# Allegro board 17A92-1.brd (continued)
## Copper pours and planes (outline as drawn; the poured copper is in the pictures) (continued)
GND on TOP: 19.34,73.56 19.2,73.7 19.2,74.07 19.12,74.14 18.29,74.14 18.13,74.3 18.13,74.86 18.21,74.93 19.73,74.93 19.83,75.03 19.83,76.1 19.94,76.2 20.9,76.2 21.05,76.05 21.05,74.07 21,74.02 20.76,74.02 20.73,74.04 20.73,74.59 20.7,74.62 20.58,74.62 20.55,74.59 20.55,74.04 20.54,74.03 20.25,74.03 20.24,74.04 20.24,74.58 20.22,74.6 20.05,74.6 20.02,74.58 20.02,74.1 20.01,74.08 19.48,74.08 19.44,74.04 19.44,73.91 19.47,73.88 20.08,73.88 20.09,73.87 20.09,73.59 20.07,73.57 19.63,73.57 19.63,73.56 ; 1 cut-out
GND on TOP: 28.37,72.81 27.51,73.67 27.51,75.06 27.2,75.37 27.2,81.49 26.44,82.25 23.79,82.25 23.47,82.57 23.47,84.84 23.66,85.03 24.37,85.03 24.95,85.61 24.95,86.64 24.99,86.68 29.48,86.68 30.43,85.73 30.43,73.42 29.82,72.81
GND on TOP: 8.44,80.35 8.44,86.04 14.13,86.04 14.13,80.35
GND on BOTTOM: 27.23,75.75 27.12,75.86 27.12,76.97 26.34,77.75 25.3,77.75 25.22,77.83 25.22,77.98 25.22,77.98 25.22,78.08 25.29,78.15 27.01,78.15 27.27,78.42 33.21,78.42 33.68,77.94 33.68,76.87 33.4,76.59 28.27,76.59 28.15,76.46 28.15,75.98 27.92,75.75 ; 3 cut-outs
GND on BOTTOM: 35.09,72.03 35.09,72.05 34.71,72.44 34.71,72.58 34.68,72.61 34.68,78.55 33.84,79.39 33.82,79.39 33.83,79.4 25.3,79.4 24.97,79.73 21.33,79.73 20.52,78.92 18.13,78.92 18.13,78.36 17.8,78.03 16.69,78.03 16.58,78.13 16.58,78.31 16,78.89 16,78.92 15.64,79.28 15.64,79.78 15.9,80.04 16.46,80.04 16.74,80.32 16.74,82.02 17.02,82.3 22.12,82.3 22.17,82.35 22.17,82.45 24.25,84.53 26.74,84.53 26.87,84.41 27.84,84.41 28.29,84.86 28.29,88.01 28.22,88.09 26.67,88.09 26.63,88.13 25.46,88.13 24.79,88.8 24.79,89.23 24.48,89.54 23.21,89.54 23.09,89.66 23.09,92.09 23.28,92.29 26.65,92.29 26.65,92.29 39.99,92.29 40.87,91.93 41.23,91.05 41.23,87.56 41.74,86.31 42.99,85.8 47.5,85.8 47.67,85.73 47.74,85.56 47.74,80.86 46.03,80.86 45.14,80.49 44.77,79.6 44.77,78.36 39.39,78.36 37.98,78.8 37.12,77.6 37.12,72.76 36.38,72.03 ; 2 cut-outs
GND on BOTTOM: outline of 227 points within 0.76,0.76 47.74,92.29 ; 6 cut-outs
GND on L2GND: 40.75,17.98 40.75,19.66 40.79,19.7 43.34,19.7 43.34,16.5 43.71,15.61 44.6,15.24 47.5,15.24 47.67,15.17 47.74,15 47.74,2 47.37,1.13 46.5,0.76 32,0.76 31.13,1.13 30.76,2 30.76,15.99 31.6,15.99 34.61,19 31.6,22.01 30.76,22.01 30.76,62.95 30.25,64.2 29,64.71 2,64.71 1.13,65.08 0.76,65.95 0.76,91.05 1.13,91.92 2,92.29 18.76,92.29 18.24,91.76 18.24,89.95 21.46,86.73 29.38,86.73 30.87,85.24 30.87,73.26 29.52,71.91 29.52,68.55 31.12,66.95 31.12,26.52 35.8,21.84 35.8,20.14 36.99,18.95 38.02,18.95 38.14,18.84 38.14,17.84 38.38,17.6 40.37,17.6
GND on L2GND: 35.47,88.32 31.5,92.29 39.99,92.29 40.86,91.92 41.23,91.05 41.23,87.56 41.74,86.31 42.99,85.8 47.5,85.8 47.67,85.73 47.74,85.56 47.74,80.86 46.03,80.86 45.14,80.49 44.77,79.6 44.77,78.36 39.39,78.36 37.98,78.8 37.12,77.6 37.12,64.1 37.98,62.9 39.39,63.34 44.77,63.34 44.77,55.51 39.39,55.51 37.98,55.95 37.12,54.75 37.12,41.25 37.98,40.05 39.39,40.49 44.77,40.49 44.77,37.46 45.14,36.56 46.03,36.19 47.5,36.19 47.67,36.13 47.74,35.96 47.74,34.31 37.9,34.31 37.01,33.94 36.64,33.05 36.64,26.94 35.94,26.94 35.9,26.98 35.9,39.63 35.42,40.11 35.42,41.53 35.85,41.96 35.85,47.53 35.47,47.91
GND on L3: outline of 109 points within 0.76,0.76 47.74,92.29
GND on L3: 35.68,26.93 35.68,34.18 35.87,34.48 36.09,34.76 36.09,40.28 35.94,40.75 35.89,41.25 35.89,46.94 35.89,46.94 35.89,47.17 35.35,47.7 35.35,88.22 31.65,91.92 31.65,92.2 31.73,92.29 39.99,92.29 40.87,91.93 41.23,91.05 41.23,87.56 41.74,86.31 42.99,85.8 47.5,85.8 47.67,85.73 47.74,85.56 47.74,80.86 46.03,80.86 45.14,80.49 44.77,79.6 44.77,78.36 39.39,78.36 37.98,78.8 37.12,77.6 37.12,64.1 37.98,62.9 39.39,63.34 44.77,63.34 44.77,55.51 39.39,55.51 37.98,55.95 37.12,54.75 37.12,45.71 37.12,45.71 37.12,41.8 37.12,41.25 37.98,40.05 39.39,40.49 44.77,40.49 44.77,37.46 45.14,36.56 46.03,36.2 47.5,36.2 47.67,36.13 47.74,35.96 47.74,34.31 37.9,34.31 37.01,33.94 36.64,33.05 36.64,26.95 36.64,26.91 36.57,26.85 35.76,26.85
GND on L3: 9.88,79.38 7.37,81.9 7.37,84.64 9.48,86.75 9.55,86.75 10.12,87.33 20.14,87.33 20.87,86.6 23.34,86.6 23.75,86.19 23.75,84.13 20.98,81.36 16.46,81.36 14.48,79.38
GND on L4: 13.59,79.28 13.59,77.65 14.17,77.07 14.17,75.08 14.96,74.3 14.96,72.54 14.27,71.86 12.32,71.86 10,74.17 10,79.33 10.09,79.41 10.09,79.43 13.44,79.43
GND on L4: outline of 123 points within 0.76,0.76 47.74,92.29
GND on L4: 37.12,68.8 36.59,68.8 35.89,69.49 35.89,75.13 31.95,79.07 27.02,79.07 26.92,79.17 25.24,79.17 25.24,79.12 24.89,78.77 24.89,72.47 24.38,71.96 19.2,71.96 19.15,72.01 19.15,73.46 18.74,73.87 17.14,73.87 15.54,75.47 15.54,81.21 16.58,82.25 25.58,82.25 26.23,82.9 26.23,86.49 25.77,86.94 23.88,86.94 23.7,87.12 23.7,87.59 24.38,88.27 24.38,89.17 23.89,89.66 23.3,89.66 23.11,89.86 23.11,91.8 23.11,91.8 23.11,92.13 23.27,92.29 39.99,92.29 40.87,91.93 41.23,91.05 41.23,87.56 41.74,86.31 42.99,85.8 47.5,85.8 47.67,85.73 47.74,85.56 47.74,80.86 46.03,80.86 45.14,80.49 44.77,79.6 44.77,78.36 39.39,78.36 37.98,78.8 37.12,77.6 37.12,74.04
GND on L4: 36.3,45.86 36.11,46.05 36.11,46.77 36.05,46.83 36.02,46.83 35.89,46.96 35.89,46.97 35.16,46.97 34.67,47.46 34.67,55.51 35.89,56.73 35.89,62.04 34.78,63.15 34.78,65.24 35.63,66.1 36.51,66.1 36.8,65.99 37.12,65.95 37.12,64.1 37.98,62.9 39.39,63.34 44.77,63.34 44.77,55.51 39.39,55.51 37.98,55.95 37.12,54.75 37.12,51.83 37.12,45.86
GND on L5VCC: outline of 122 points within 0.76,0.76 47.74,92.29
3D3V_GSEN2 on TOP: 17.1,72.43 16.81,72.72 16.81,75.55 17.67,76.41 19.38,76.41 19.45,76.33 19.45,75.21 19.33,75.08 18.08,75.08 17.93,74.93 17.93,74.04 17.98,73.99 18.92,73.99 19,73.92 19,73.59 19.21,73.37 20.05,73.37 20.08,73.34 20.08,73.08 20.06,73.07 19.36,73.07 19.34,73.04 19.34,72.88 19.36,72.85 20.02,72.85 20.03,72.84 20.03,72.47 20.02,72.46 18.87,72.46 18.85,72.43 ; 3 cut-outs
3D3V_MCU on TOP: 4.83,77.83 4.75,77.91 4.75,78.65 4.82,78.72 5.39,78.72 5.54,78.88 5.54,80.25 5.9,80.6 8.18,80.6 8.18,80.17 8.23,80.12 8.66,80.12 8.69,80.1 8.69,79.18 8.38,78.88 6.76,78.88 6.67,78.79 6.67,78.06 6.44,77.83 ; 3 cut-outs
3D3V_MCU on TOP: 7.02,86.29 6.8,86.51 6.8,87.47 6.96,87.64 7.47,87.64 7.6,87.77 7.6,89.29 7.8,89.49 8.03,89.49 8.44,89.9 8.44,90.51 8.34,90.61 7.2,90.61 6.57,89.98 5.87,89.98 5.77,90.08 5.77,91.12 6,91.35 7.87,91.35 8.18,91.04 9.1,91.04 9.39,90.74 9.39,89.69 9.05,89.35 8.72,89.35 8.49,89.11 8.49,87.51 8.66,87.33 8.66,87.33 8.68,87.31 8.68,86.31 8.66,86.29
AUD_AGND on BOTTOM: 34.44,31.65 34.34,31.75 34.34,32.26 34.31,32.29 34.13,32.29 33.96,32.46 33.96,32.84 34.29,33.17 35.3,33.17 35.43,33.05 35.43,31.8 35.28,31.65 ; 1 cut-out
AUD_AGND on BOTTOM: 33.93,27.82 33.65,28.09 33.65,29.09 33.47,29.26 32.46,29.26 32.33,29.14 32.33,28.93 32.28,28.88 31.61,28.88 31.28,29.21 31.28,31.67 31.38,31.76 32.21,31.76 32.46,31.51 32.46,30.25 33.2,30.25 34.21,29.24 34.8,29.24 35.07,28.96 35.07,28.17 34.72,27.82 ; 4 cut-outs
AUD_AGND on BOTTOM: 10.35,82.54 10.15,82.75 9.77,82.75 9.36,83.15 9.36,91.03 9.52,91.2 11.38,91.2 11.38,91.19 13.68,91.19 13.92,90.96 13.92,89.84 13.48,89.41 12.09,89.41 11.96,89.28 11.96,88.57 11.94,88.55 10.5,88.55 10.33,88.37 10.33,83.11 10.58,82.86 11.96,82.86 11.99,82.82 11.99,82.59 11.94,82.54
AUD_AGND on L2GND: 40.37,19.82 40.37,18.14 40.21,17.98 38.54,17.98 38.52,18 38.52,18.99 38.18,19.33 37.15,19.33 36.18,20.3 36.18,22 31.51,26.67 31.51,67.11 29.91,68.71 29.91,71.75 31.25,73.1 31.25,85.4 29.54,87.11 21.62,87.11 18.62,90.11 18.62,91.6 19.1,92.09 31.16,92.09 35.09,88.16 35.09,47.75 35.47,47.37 35.47,42.12 35.04,41.69 35.04,39.95 35.52,39.47 35.52,26.82 35.78,26.56 36.7,26.56 37.16,25.93 37.9,25.69 47.74,25.69 47.74,23 47.67,22.83 47.5,22.76 44.6,22.76 43.71,22.39 43.34,21.5 43.34,20.08 40.63,20.08
AUD_AGND on L4: 23.74,88.72 23.74,88.64 22.61,87.51 18.11,87.51 13.52,82.92 12.32,82.92 11.94,82.54 10.36,82.54 10.16,82.74 9.75,82.74 9.17,83.32 9.17,91.63 9.82,92.27 22.3,92.27 22.62,91.95 22.62,89.48 22.94,89.15 23.53,89.15 23.74,88.94
AUD_AGND on L5VCC: 35.02,38.79 35.3,38.51 37.92,38.51 38.51,37.92 44.77,37.92 44.77,37.46 45.14,36.56 46.03,36.19 47.5,36.19 47.67,36.13 47.74,35.96 47.74,34.31 37.9,34.31 37.01,33.94 36.64,33.05 36.64,26.95 37.01,26.06 37.9,25.69 39.37,25.69 39.37,25.22 38.23,24.08 33.11,24.08 32.97,24.22 32.97,25.14 33.73,25.9 33.73,28.92 33.36,29.29 32.5,29.29 32.09,28.88 31.71,28.88 31.43,29.17 31.43,33.21 31.53,33.31 31.94,33.31 32.45,32.8 33.23,32.8 33.62,33.19 33.62,34.41 33.09,34.95 31.69,34.95 31.57,35.06 31.57,36.89 31.92,37.24 31.92,38.05 31.45,38.52 31.45,42.5 31.59,42.65 31.99,42.65 32.22,42.41 33.12,42.41 34.23,41.3 34.23,39.76 34.51,39.48 35.02,39.48
AUD_AGND on L5VCC: 12.32,82.9 11.95,82.53 10.36,82.53 10.16,82.73 9.75,82.73 9.17,83.32 9.17,91.58 9.8,92.22 9.8,92.29 22.32,92.29 22.32,92.24 22.66,91.91 22.66,89.41 22.89,89.18 23.57,89.18 23.77,88.98 23.77,88.58 22.64,87.45 18.17,87.45 13.62,82.9
RING2_HPMIC1 on BOTTOM: 31.65,35.05 31.42,35.28 31.42,36.53 32.08,37.19 32.08,38.31 31.65,38.74 31.62,38.74 31.59,38.76 31.59,40.62 31.65,40.67 32.64,40.67 32.76,40.54 32.76,39.63 32.94,39.45 33.22,39.45 33.37,39.3 33.37,38.15 33.8,37.72 35.3,37.72 35.56,37.47 35.56,36.83 35.34,36.61 33.03,36.61 32.46,36.04 32.46,35.33 32.18,35.05 ; 2 cut-outs
RING2_HPMIC1 on L4: 34.08,37.77 36.99,37.77 37.12,37.63 37.12,36.92 36.75,36.56 34.15,36.56 33.91,36.79 33.91,37.6
RING2_R on BOTTOM: 10.79,86.04 10.58,86.25 10.58,87.72 10.72,87.86 12.58,87.86 12.58,87.86 13.14,87.86 16.64,91.37 20.1,91.37 20.19,91.28 20.19,90.62 19.97,90.4 17.17,90.4 12.81,86.04
RING2_R on BOTTOM: 33.09,39.58 32.98,39.68 32.98,40.84 32.52,41.31 31.61,41.31 31.47,41.45 31.47,42.64 31.62,42.79 31.97,42.79 32.29,42.47 33.12,42.47 34.14,41.45 34.14,39.82 33.9,39.58
RING2_R on L3: 31.5,41.28 32.99,41.28 33.15,41.45 33.15,43.42 33.16,43.42 33.12,43.46 32.03,43.46 31.96,43.39 31.54,43.39 31.41,43.26 31.41,41.37
RING2_R on L3: 20.21,90.08 20.21,91.25 20,91.46 18.84,91.46 18.65,91.27 18.65,90.09 19.59,89.15 20.08,89.15 20.37,89.44 20.37,89.92
SLEEVE_HPMIC1 on TOP: 40.74,21.72 40.69,21.77 40.69,22.74 40.82,22.86 40.82,23.62 41.04,23.85 42.92,23.85 43.33,23.45 43.33,22.4 42.64,21.72 ; 2 cut-outs
SLEEVE_R on TOP: 39.85,20.2 39.4,20.65 39.4,22.61 39.5,22.71 40.32,22.71 40.42,22.61 40.42,21.66 40.57,21.52 41.29,21.52 41.43,21.39 41.43,20.26 41.36,20.2
SLEEVE_R on BOTTOM: 34.9,34.81 34.76,34.95 34.76,36.2 34.99,36.43 35.5,36.43 36,36.93 36,37.56 36.17,37.73 37.97,37.73 38.11,37.59 38.11,36.39 37.9,36.18 36.93,36.18 35.57,34.81
SLEEVE_R on BOTTOM: 10.76,84.04 10.62,84.19 10.62,85.69 10.77,85.85 12.93,85.85 17.12,90.04 19.77,90.04 19.77,90.04 20,90.04 20.51,90.56 22.35,90.56 22.49,90.41 22.49,89.61 22.34,89.46 20.68,89.46 20.67,89.45 20.24,89.02 17.56,89.02 12.58,84.04
SLEEVE_R on L3: 35.4,36.71 35.52,36.6 35.52,35.33 35.54,35.32 35.54,34.54 35.3,34.31 33.11,34.31 32.9,34.52 32.9,36.45 33.17,36.71
SLEEVE_R on L3: 39.7,20.39 40,20.09 41.74,20.09 41.97,20.32 41.97,21.97 41.97,21.97 41.97,22.51 41.77,22.71 39.97,22.71 39.7,22.44
SLEEVE_R on L3: 20.75,90.62 23.4,90.62 23.55,90.47 23.55,89.6 23.37,89.42 22.53,89.42 22.5,89.45 20.93,89.45 20.62,89.75 20.62,90.49
USB20_VCCA on BOTTOM: 31.21,43.44 31.14,43.51 31.14,45.83 31.29,45.98 36.87,45.98 36.87,43.95 36.36,43.44 ; 3 cut-outs
USB20_VCCA on BOTTOM: 32.59,66.56 31.98,67.17 31.98,69.22 31.5,69.71 31.5,73.47 31.33,73.64 28.65,73.64 28.45,73.85 28.45,76.13 28.78,76.46 33.41,76.46 33.76,76.11 33.76,72.22 36.87,69.11 36.87,66.56 ; 6 cut-outs
USB20_VCCA on L4: 31.07,72.02 27.49,75.59 25.58,75.59 25.22,75.95 25.22,78.16 25.58,78.52 31.98,78.52 35.66,74.84 35.66,70.96 36.87,69.76 36.87,66.26 36.84,66.29 35.49,66.29 34.64,65.45 34.64,62.98 35.55,62.07 35.55,56.56 34.51,55.52 34.51,47.29 35,46.8 35.79,46.8 35.96,46.63 35.96,46 36.27,45.69 36.8,45.69 36.8,45.69 36.99,45.69 37.07,45.61 37.07,43.9 36.82,43.66 35.21,43.66 34.94,43.39 31.62,43.39 31.29,43.72 31.29,46.38 31.75,46.84 31.75,65.2 31.07,65.88

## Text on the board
Ref Des/Silkscreen Top: Drax 11 MLK AMD IO | 17A92-1 | CD38F | MADE IN TAIWAN | X601:12MHZ
User.27: ByImpedance:100.0@_REF_L2=("4.0/5.5(L3)")|_REF_L1=("5.0/4.0(L3)")|_REF_L6=("5.0/4.0(L4)")|Type="DP"|_REF_L4=("3.5/4.5(L2/L5)")|_REF_L3=("3.5/4.5(L2/L5)")|imp="100.0" | ByImpedance:40.0@_REF_L2=("3.5(L1/L3)" "10.0(L3)")|_REF_L1=("5.5(L2)")|_REF_L6=("5.5(L5)")|Type="SE"|_REF_L4=("8.51(L3/L5)" "8.5(L2/L5)")|_REF_L3=("8.5(L2/L5)")|imp="40.0" | ByImpedance:45.0@_REF_L2=("8.0(L3)")|_REF_L1=("4.5(L2)")|_REF_L6=("4.5(L5)")|Type="SE"|_REF_L4=("7.0(L2/L5)")|_REF_L3=("7.0(L2/L5)")|imp="45.0" | ByImpedance:48.0@_REF_L2=("7.0(L3)")|_REF_L1=("4.0(L2)")|_REF_L6=("4.0(L5)")|Type="SE"|_REF_L4=("6.0(L2/L5)")|_REF_L3=("6.0(L2/L5)")|imp="48.0" | ByImpedance:50.0@_REF_L2=("6.5(L3)")|_REF_L1=("3.5(L2)")|_REF_L6=("3.5(L5)")|Type="SE"|_REF_L4=("5.5(L2/L5)" "5.51(L3/L5)")|_REF_L3=("5.5(L2/L5)")|imp="50.0" | ByImpedance:52.0@_REF_L2=("6.0(L3)")|_REF_L1=("3.0(L2)")|_REF_L6=("3.0(L5)")|Type="SE"|_REF_L4=("5.0(L2/L5)")|_REF_L3=("5.0(L2/L5)")|imp="52.0" | ByImpedance:55.0@_REF_L2=("5.0(L3)")|Type="SE"|_REF_L4=("4.5(L2/L5)")|_REF_L3=("4.5(L2/L5)")|imp="55.0" | ByImpedance:72.0@_REF_L2=("8.0/4.0(L3)")|_REF_L1=("5.5/5.0(L2)")|_REF_L6=("5.5/5.0(L5)")|Type="DP"|_REF_L4=("7.5/4.0(L2/L5)")|_REF_L3=("7.5/4.0(L2/L5)")|imp="72.0" | ByImpedance:80.0@_REF_L2=("6.0/4.0(L3)")|_REF_L1=("4.5/5.0(L2)")|_REF_L6=("4.5/5.0(L5)")|Type="DP"|_REF_L4=("6.0/4.0(L2/L5)")|_REF_L3=("6.0/4.0(L2/L5)")|imp="80.0" | ByImpedance:83.0@_REF_L2=("5.5/4.0(L3)")|_REF_L1=("4.0/5.0(L2)")|_REF_L6=("4.0/5.0(L5)")|Type="DP"|_REF_L4=("5.51/4.0(L3/L5)" "5.5/4.0(L2/L5)")|_REF_L3=("5.5/4.0(L2/L5)")|imp="83.0" | ByImpedance:85.0@_REF_L2=("5.0/4.0(L3)")|_REF_L1=("3.5/4.5(L2)")|_REF_L6=("3.5/4.5(L5)")|Type="DP"|_REF_L4=("5.0/4.0(L2/L5)" "5.1/4.0(L3/L5)")|_REF_L3=("5.0/4.0(L2/L5)")|imp="85.0" | ByImpedance:90.0@_REF_L2=("5.0/5.0(L3)")|_REF_L1=("3.5/6.0(L2)")|_REF_L6=("3.5/6.0(L5)")|Type="DP"|_REF_L4=("4.5/4.0(L2/L5)")|_REF_L3=("4.5/4.0(L2/L5)")|imp="90.0" | LayerIndex:nil | Source:6-1.0-8d.xls | artWorks:("_REF_L3" "_REF_L4" "_REF_L6" "_REF_L2" "_REF_L1") | gtImpOutlineUsed:BOARD GEOMETRY/OUTLINE
User.28: Board Accuracy Check,Dec 12 16:02:05 2017,Passed | Dummy-Static-No Shape On Layer Check,Dec 12 16:02:06 2017,Passed | Split Plane Check,Dec 20 20:25:24 2015,Passed
User.36: GND | AUD_AGND
User.37: AUD_AGND | GND
User.40: This gerber is just for your reference to find the DP impedance traces in layer L1. | DP IMPEDANCE TABLE: L1 | * - Denotes that this Impedance | is NOT used | IMP(Ohm) | *72.0 | *80.0 | *83.0 | *85.0 | 90.0 | *100.0 | WIDTH(mils) | 5.5/5.0 | 4.5/5.0 | 4.0/5.0 | 3.5/4.5 | 3.5/6.0 | 5.0/4.0 | TYPE | DP | Ref. Plane | L2 | L3
User.42: This gerber is just for your reference to find the SE impedance traces in layer L1. | SE IMPEDANCE TABLE: L1 | * - Denotes that this Impedance | is NOT used | IMP(Ohm) | *40.0 | *45.0 | *48.0 | 50.0 | *52.0 | WIDTH(mils) | 5.5 | 4.5 | 4.0 | 3.5 | 3.0 | TYPE | SE | Ref. Plane | L2
User.44: This gerber is just for your reference to find the DP impedance traces in layer L2. | DP IMPEDANCE TABLE: L2 | * - Denotes that this Impedance | is NOT used | IMP(Ohm) | *72.0 | *80.0 | *83.0 | *85.0 | *90.0 | *100.0 | WIDTH(mils) | 8.0/4.0 | 6.0/4.0 | 5.5/4.0 | 5.0/4.0 | 5.0/5.0 | 4.0/5.5 | TYPE | DP | Ref. Plane | L3
User.45: Note:Refer to DRILL layer for ELLIPSE drill direction | FIGURE | SIZE | 10.0 | 16.0 | 28.0 | 99.0 | 119.0 | 56.0x20.0 | 71.0x32.0 | 103.0x32.0 | 130.0x118.0 | DRILL CHART: TOP to BOTTOM | ALL UNITS ARE IN MILS | PLATED | NON-PLATED | QTY | 279 | 28 | 8 | 1 | 6 | 4 | This gerber is just for your reference to find the DP impedance traces in layer L3. | This gerber is just for your reference to find the DP impedance traces in layer L4. | This gerber is just for your reference to find the DP impedance traces in layer L6. | This gerber is just for your reference to find the SE impedance traces in layer L2. | This gerber is just for your reference to find the SE impedance traces in layer L3. | This gerber is just for your reference to find the SE impedance traces in layer L4. | This gerber is just for your reference to find the SE impedance traces in layer L6. | DP IMPEDANCE TABLE: L3 | DP IMPEDANCE TABLE: L4 | DP IMPEDANCE TABLE: L6 | SE IMPEDANCE TABLE: L2 | SE IMPEDANCE TABLE: L3 | SE IMPEDANCE TABLE: L4 | SE IMPEDANCE TABLE: L6 | * - Denotes that this Impedance | is NOT used | Model | Drax 11 MLK AMD IO | IMP(Ohm) | *40.0 | *72.0 | *45.0 | *80.0 | *48.0 | *83.0 | *85.0 | 50.0 | *50.0 | *52.0 | *90.0 | 90.0 | *100.0 | *55.0 | PCB_NO | 17A92 | VER. | WIDTH(mils) | 3.5 | 5.5 | 8.5 | 4.5 | 7.0 | 4.0 | 6.0 | 8.0 | 3.0 | 5.0 | 6.5 | 5.5/5.0 | 8.51 | 4.5/5.0 | 4.0/5.0 | 3.5/4.5 | 3.5/6.0 | 5.0/4.0 | 5.51 | 7.5/4.0 | 6.0/4.0 | 5.5/4.0 | 4.5/4.0 | 5.51/4.0 | 5.1/4.0 | Layer | DRILL | L1 | L2GND | L3 | TMASK | TPLACE | TSILK | TSMD | TYPE | SE | DP | Designer | WENDY | Ref. Plane | L1/L3 | L2/L5 | L5 | L3/L5 | L4 | Date | 12/12/2017 | BMASK | BPLACE | BSILK | BSMD | L5VCC | L6
